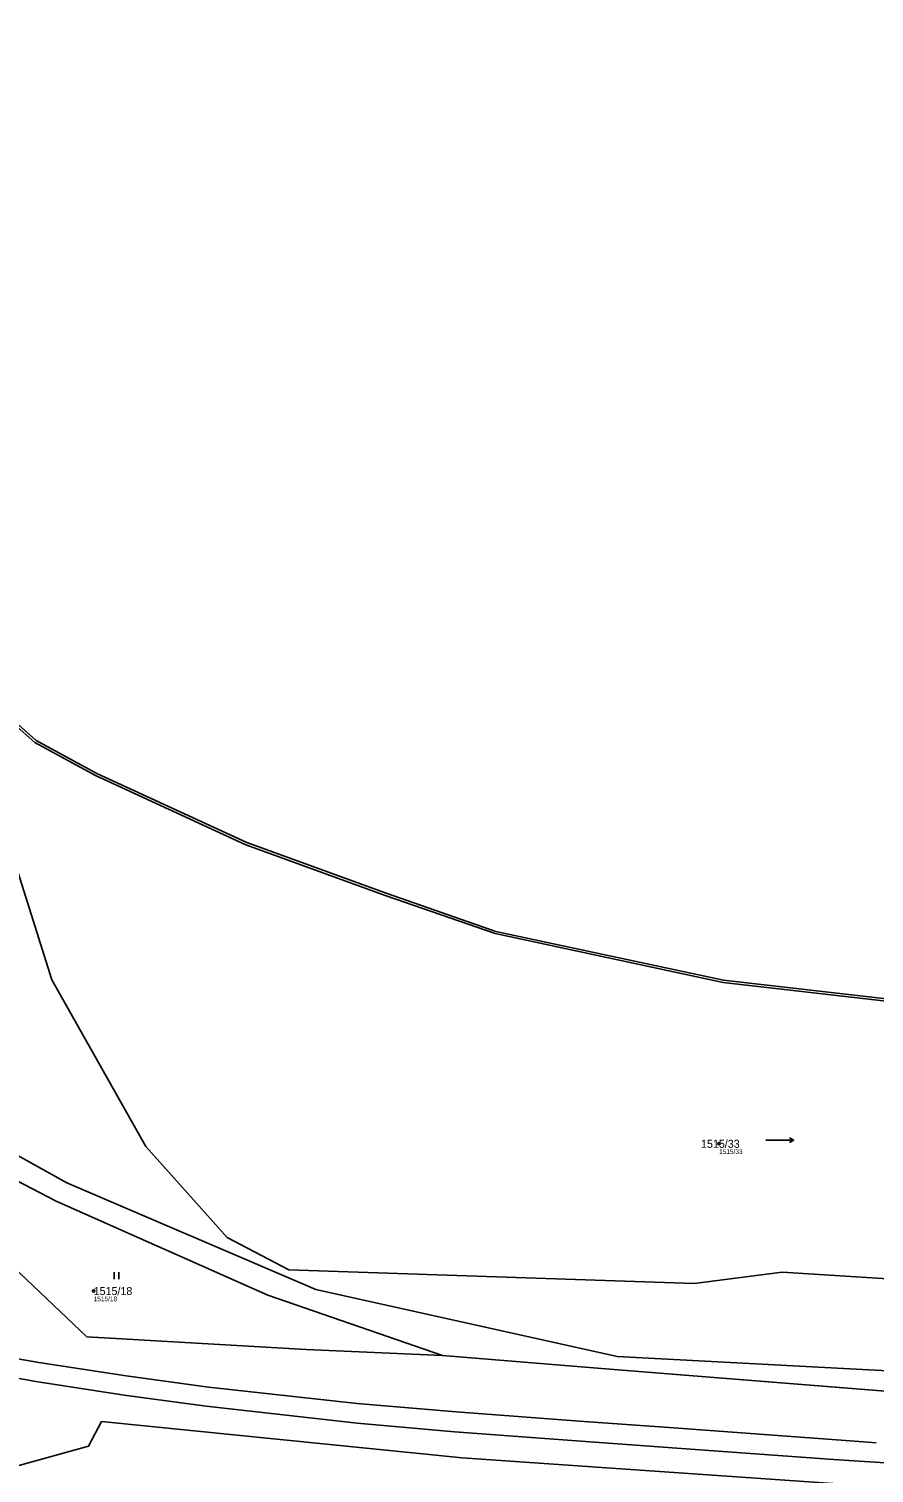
# Model space of a CAD drawing. Extents: x -770088 to -765625, y -1057899 to -1053934.
# Drawn here: x -767359.5 to -767179.8, y -1054979.1 to -1054672.3 of the extents above; entities that cross this region are included whole.
import ezdxf

# ---------------------------------------------------------------- set-up
doc = ezdxf.new("R2010")
doc.units = 0
for name, color, linetype in [('Definiční body', 7, 'Continuous'), ('Hranice parcel', 7, 'Continuous'), ('Parcelní čísla', 7, 'Continuous'), ('Polygon ku', 7, 'Continuous'), ('Polygon parcely', 7, 'Continuous'), ('Poz předměty', 7, 'Continuous'), ('Vnitřní kresba', 7, 'Continuous'), ('Značky kultur', 7, 'Continuous')]:
    doc.layers.add(name, color=color, linetype=linetype)

msp = doc.modelspace()

# ---------------------------------------------------------------- linework, layer by layer
at = {"layer": 'Definiční body'}
for centre in [(-767212.78, -1054909.13), (-767345.71, -1054940.41)]:
    msp.add_circle(centre, 0.25, dxfattribs=at)
at = {"layer": 'Hranice parcel'}
for p, q in [((-767385.74, -1054799), (-767357.9, -1054823.47)), ((-767357.9, -1054823.47), (-767345.05, -1054830.51)), ((-767283.35, -1054855.99), (-767260.21, -1054864.01)), ((-767235.16, -1054957.04), (-767271.59, -1054954.11)), ((-767152.63, -1054963.64), (-767235.16, -1054957.04))]:
    msp.add_line(p, q, dxfattribs=at)
for points in [[(-767042.8, -1054855.07), (-767096.48, -1054918.48), (-767145.53, -1054939.79), (-767199.4, -1054936.37), (-767218.08, -1054938.78), (-767304.22, -1054935.91), (-767317.34, -1054929.04), (-767334.65, -1054909.7), (-767354.59, -1054874.29), (-767364.17, -1054843.9), (-767376.37, -1054815.85), (-767392.88, -1054792.13)], [(-767345.05, -1054830.51), (-767313.16, -1054845.16), (-767283.35, -1054855.99)], [(-767260.21, -1054864.01), (-767211.84, -1054874.41), (-767140.17, -1054882.61), (-767111.97, -1054876.78)], [(-767396.53, -1054896.85), (-767384.33, -1054905.37), (-767353.65, -1054921.35), (-767308.71, -1054941.25), (-767271.59, -1054954.11)], [(-767040.18, -1054987.39), (-767182.41, -1054981.69), (-767267.36, -1054975.85), (-767344.04, -1054968.14), (-767346.77, -1054973.36), (-767372.36, -1054980.44), (-767381.09, -1054971.25), (-767376.02, -1054961.44), (-767462.61, -1054944.07), (-767479.62, -1054945.09), (-767514.25, -1054935.59)], [(-767271.59, -1054954.11), (-767300.52, -1054952.79), (-767347.13, -1054950.16), (-767361.37, -1054936.62)]]:
    msp.add_lwpolyline(points, dxfattribs=at)
at = {"layer": 'Polygon ku'}
msp.add_lwpolyline([(-767140.17, -1054882.61), (-767211.84, -1054874.41), (-767260.21, -1054864.01), (-767283.35, -1054855.99), (-767313.16, -1054845.16), (-767345.05, -1054830.51), (-767357.9, -1054823.47), (-767385.74, -1054799), (-767392.88, -1054792.13), (-767401.13, -1054784.2), (-767451.03, -1054719.22), (-767464.13, -1054702.17), (-767478.92, -1054681.98), (-767481.23, -1054678.81), (-767489.54, -1054668.82)], dxfattribs=at)
at = {"layer": 'Polygon parcely'}
for points in [[(-767598.77, -1054667.38), (-767583.46, -1054683.97), (-767570.6, -1054699.53), (-767553.01, -1054720.74), (-767548.24, -1054726.86), (-767529.81, -1054752.17), (-767531.4, -1054753.92), (-767494.87, -1054803.63), (-767486.78, -1054814.3), (-767480.71, -1054822.3), (-767478.57, -1054825.04), (-767459.71, -1054846.05), (-767441.46, -1054863.83), (-767432.66, -1054871.36), (-767407.07, -1054889.96), (-767396.53, -1054896.85), (-767384.33, -1054905.37), (-767353.65, -1054921.35), (-767308.71, -1054941.25), (-767271.59, -1054954.11), (-767235.16, -1054957.04), (-767152.63, -1054963.64)], [(-767145.53, -1054939.79), (-767199.4, -1054936.37), (-767218.08, -1054938.78), (-767304.22, -1054935.91), (-767317.34, -1054929.04), (-767334.65, -1054909.7), (-767354.59, -1054874.29), (-767364.17, -1054843.9), (-767376.37, -1054815.85)], [(-767725.45, -1054824.62), (-767692.81, -1054850), (-767618, -1054893.61), (-767573.93, -1054913.24), (-767524.16, -1054929.28), (-767514.25, -1054935.59), (-767479.62, -1054945.09), (-767462.61, -1054944.07), (-767376.02, -1054961.44), (-767381.09, -1054971.25), (-767372.36, -1054980.44), (-767346.77, -1054973.36), (-767344.04, -1054968.14), (-767267.36, -1054975.85), (-767182.41, -1054981.69)], [(-767040.18, -1054987.39), (-767182.41, -1054981.69), (-767267.36, -1054975.85), (-767344.04, -1054968.14), (-767346.77, -1054973.36), (-767372.36, -1054980.44), (-767381.09, -1054971.25), (-767376.02, -1054961.44), (-767462.61, -1054944.07), (-767479.62, -1054945.09), (-767514.25, -1054935.59), (-767549.86, -1054975.62), (-767508.25, -1054990.79), (-767472.4, -1054967.24), (-767447.46, -1054960.98), (-767423.39, -1054971.25), (-767398.03, -1055002.58), (-767368.4, -1055013.68), (-767367.33, -1054994.3), (-767343.15, -1054986.96), (-767306.46, -1055021.07), (-767217.76, -1055015.77), (-767308.49, -1055055.25), (-767109.8, -1055069.97)], [(-767152.63, -1054963.64), (-767235.16, -1054957.04), (-767271.59, -1054954.11), (-767300.52, -1054952.79), (-767347.13, -1054950.16), (-767361.37, -1054936.62)]]:
    msp.add_lwpolyline(points, dxfattribs=at)
for points in [[(-767392.88, -1054792.13), (-767376.37, -1054815.85), (-767364.17, -1054843.9), (-767354.59, -1054874.29), (-767334.65, -1054909.7), (-767317.34, -1054929.04), (-767304.22, -1054935.91), (-767218.08, -1054938.78), (-767199.4, -1054936.37), (-767145.53, -1054939.79), (-767096.48, -1054918.48), (-767042.8, -1054855.07), (-767090.1, -1054869.34), (-767111.97, -1054876.78), (-767140.17, -1054882.61), (-767211.84, -1054874.41), (-767260.21, -1054864.01), (-767283.35, -1054855.99), (-767313.16, -1054845.16), (-767345.05, -1054830.51), (-767357.9, -1054823.47), (-767385.74, -1054799)], [(-767361.37, -1054936.62), (-767347.13, -1054950.16), (-767300.52, -1054952.79), (-767271.59, -1054954.11), (-767308.71, -1054941.25), (-767353.65, -1054921.35), (-767384.33, -1054905.37), (-767396.53, -1054896.85), (-767392.17, -1054903.35)]]:
    msp.add_lwpolyline(points, close=True, dxfattribs=at)
at = {"layer": 'Poz předměty'}
for p, q in [((-767381.22, -1054951.38), (-767357.37, -1054955.59)), ((-767358.01, -1054959.6), (-767379.43, -1054955.84)), ((-767357.37, -1054955.59), (-767338.8, -1054958.44)), ((-767339.24, -1054962.51), (-767358.01, -1054959.6)), ((-767338.8, -1054958.44), (-767321.33, -1054960.79)), ((-767321.33, -1054960.79), (-767289.68, -1054964.28)), ((-767321.83, -1054964.89), (-767339.24, -1054962.51)), ((-767289.68, -1054964.28), (-767268.69, -1054966.08)), ((-767289.71, -1054968.45), (-767321.83, -1054964.89)), ((-767268.69, -1054966.08), (-767242.48, -1054968.03)), ((-767268.98, -1054970.28), (-767289.71, -1054968.45)), ((-767243.06, -1054972.24), (-767268.98, -1054970.28)), ((-767242.48, -1054968.03), (-767221.5, -1054969.55)), ((-767221.5, -1054969.55), (-767184.9, -1054972.21)), ((-767221.77, -1054973.78), (-767243.06, -1054972.24)), ((-767184.9, -1054972.21), (-767179.38, -1054972.61)), ((-767189.48, -1054976.09), (-767221.77, -1054973.78)), ((-767185.21, -1054976.39), (-767189.48, -1054976.09)), ((-767149.09, -1054978.65), (-767185.21, -1054976.39))]:
    msp.add_line(p, q, dxfattribs=at)
at = {"layer": 'Vnitřní kresba'}
for p, q in [((-767386.04, -1054799.4), (-767358.2, -1054823.88)), ((-767358.2, -1054823.88), (-767345.31, -1054830.94)), ((-767345.31, -1054830.94), (-767313.33, -1054845.63)), ((-767313.33, -1054845.63), (-767283.52, -1054856.46)), ((-767283.52, -1054856.46), (-767260.34, -1054864.49)), ((-767260.34, -1054864.49), (-767211.92, -1054874.9)), ((-767211.92, -1054874.9), (-767140.16, -1054883.12)), ((-767416.95, -1054881.02), (-767351.42, -1054917.45)), ((-767298.48, -1054940.09), (-767351.42, -1054917.45)), ((-767234.41, -1054954.29), (-767298.48, -1054940.09)), ((-767234.41, -1054954.29), (-767153.67, -1054958.62))]:
    msp.add_line(p, q, dxfattribs=at)
at = {"layer": 'Značky kultur'}
for p, q in [((-767202.86, -1054908.36), (-767196.86, -1054908.36)), ((-767196.86, -1054908.36), (-767197.84, -1054907.86)), ((-767196.86, -1054908.36), (-767197.84, -1054908.86)), ((-767341.35, -1054937.89), (-767341.35, -1054936.39)), ((-767340.35, -1054937.89), (-767340.35, -1054936.39))]:
    msp.add_line(p, q, dxfattribs=at)

# ---------------------------------------------------------------- texts
at = {"layer": 'Definiční body'}
for s, p in [('1515/33', (-767212.78, -1054911.29)), ('1515/18', (-767345.71, -1054942.57))]:
    msp.add_text(s, height=1, dxfattribs=at).set_placement(p)
at = {"layer": 'Parcelní čísla'}
for s, p in [('1515/33', (-767216.62, -1054909.98)), ('1515/18', (-767345.71, -1054941.26))]:
    msp.add_text(s, height=1.7, dxfattribs=at).set_placement(p)

doc.saveas('drawing.dxf')
